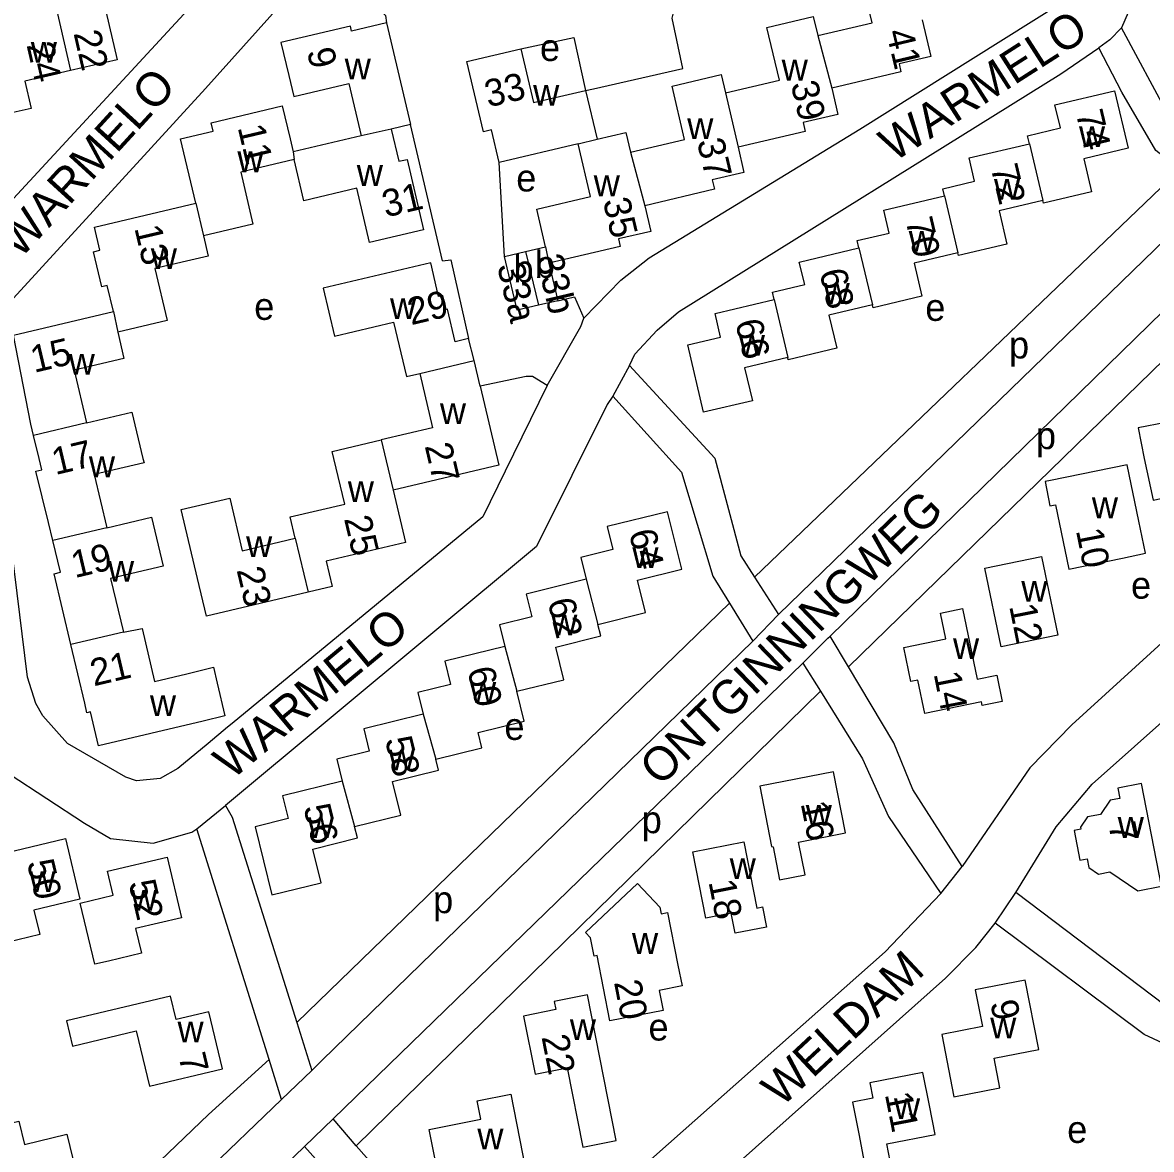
# Model space of a CAD drawing. Extents: x 157646 to 159241, y 379213 to 381217.
# Drawn here: x 158162.1 to 158329.1, y 380397.8 to 380564.5 of the extents above; entities that cross this region are included whole.
import ezdxf

# ---------------------------------------------------------------- set-up
doc = ezdxf.new("R2010")
doc.units = 0
for name, color, linetype in [('BLT_Basislijn', 7, 'Continuous'), ('BLT_Bebouwing', 7, 'Continuous'), ('BLT_Centroide', 7, 'Continuous'), ('BLT_Huisnummer', 7, 'Continuous'), ('BLT_Huisnummer_ tussenligend', 7, 'Continuous'), ('BLT_Onderverdeling_panden', 7, 'Continuous'), ('BLT_Straatnaam', 7, 'Continuous')]:
    doc.layers.add(name, color=color, linetype=linetype)

msp = doc.modelspace()

# ---------------------------------------------------------------- linework, layer by layer
at = {"layer": 'BLT_Basislijn'}
for p, q in [((158233.4, 380529.9), (158232.59, 380543.79)), ((158333.3, 380542.79), (158270.39, 380482.44)), ((158338.15, 380539.27), (158273.9, 380476.9)), ((158281.54, 380473.72), (158341.93, 380532.68)), ((158345.48, 380528.82), (158284.27, 380469.15)), ((158251.9, 380513.75), (158249.43, 380509.21)), ((158270.39, 380482.44), (158273.9, 380476.9)), ((158266.66, 380478.58), (158202.66, 380416.55)), ((158266.66, 380478.58), (158270.13, 380472.97)), ((158273.9, 380476.9), (158270.13, 380472.97)), ((158270.13, 380472.97), (158206.43, 380410.96)), ((158277.5, 380469.74), (158281.24, 380473.43)), ((158281.24, 380473.43), (158281.54, 380473.72)), ((158284.27, 380469.15), (158281.54, 380473.72)), ((158277.5, 380469.74), (158208.05, 380402.3)), ((158277.5, 380469.74), (158280.12, 380465.55)), ((158280.12, 380465.55), (158211.47, 380398.29)), ((158187.89, 380445.21), (158192.12, 380448.67)), ((158198.57, 380411.07), (158187.89, 380445.21)), ((158297.95, 380435.63), (158301.07, 380439.61)), ((158305.95, 380431.25), (158309.01, 380435.78)), ((158202.66, 380416.55), (158204.88, 380409.47)), ((158200.42, 380405.17), (158198.57, 380411.07)), ((158204.88, 380409.47), (158206.43, 380410.96)), ((158200.42, 380405.17), (158204.88, 380409.47)), ((158168.55, 380374.51), (158200.42, 380405.17)), ((158203.81, 380398.22), (158208.05, 380402.3)), ((158211.47, 380398.29), (158208.05, 380402.3)), ((158203.81, 380398.22), (158139.69, 380336.38)), ((158203.81, 380398.22), (158207.13, 380394.51)), ((158211.47, 380398.29), (158231.68, 380375.57))]:
    msp.add_line(p, q, dxfattribs=at)
for points in [[(158175.77, 380635.43), (158161.21, 380631.77), (158156.75, 380630.24), (158148.79, 380625.89), (158142.68, 380620.8), (158139.58, 380617.09), (158122.17, 380593.19), (158088.91, 380548.79), (158087.38, 380546.5), (158085.15, 380541.88), (158083.98, 380537.65), (158083.7, 380528.68), (158092.89, 380456.03), (158094.64, 380453.46), (158097.98, 380452.14), (158149.23, 380463.59), (158151.12, 380464.15), (158152.81, 380465.76), (158153.39, 380468.79), (158147.46, 380517.85), (158147.9, 380522.87), (158148.44, 380524.46), (158150.49, 380527.42), (158204.53, 380585.91)], [(158245.14, 380520.77), (158250.62, 380526.37), (158254.8, 380529.71), (158285.96, 380548.74), (158315.78, 380567.4), (158317.48, 380571.03), (158317.34, 380574.69), (158312.89, 380594.77), (158310.67, 380597.7), (158308.56, 380598.87), (158304.79, 380599.21), (158304.38, 380599.21)], [(158320.81, 380598.41), (158321.35, 380597.47), (158322.52, 380593.15), (158326.84, 380572.7), (158326.63, 380568.3), (158324.66, 380563.71)], [(158245.37, 380554.46), (158246.58, 380554.68), (158259.79, 380557.7), (158258.19, 380565.13), (158258.38, 380565.93), (158277.39, 380570.67), (158277.63, 380570.93), (158277.57, 380571.67), (158274.44, 380584.86)], [(158192.44, 380460.23), (158189.56, 380457.85), (158185.09, 380454.13), (158182.48, 380452.66), (158178.96, 380452.33), (158177.37, 380452.85), (158168.77, 380457.81), (158165.12, 380461.91), (158164.05, 380463.75), (158162.83, 380467.65), (158157.4, 380511.32), (158157.32, 380517.6), (158158.75, 380521.1), (158160.25, 380523.11), (158189.19, 380554.74), (158206.48, 380574.08)], [(158206.48, 380574.08), (158215.77, 380565.54), (158215.93, 380564.47)], [(158324.66, 380563.71), (158322.93, 380561.92), (158321.31, 380560.74)], [(158337.01, 380546.43), (158331.69, 380550.62), (158324.66, 380563.71)], [(158235.82, 380560.61), (158243.66, 380562.28), (158245.37, 380554.46)], [(158251.9, 380513.75), (158252.68, 380515.43), (158255.97, 380519), (158259.14, 380521.72), (158315.7, 380556.9), (158321.31, 380560.74)], [(158333.3, 380542.79), (158329.75, 380545.57), (158324.69, 380554.22), (158321.31, 380560.74)], [(158223.04, 380534.29), (158219.48, 380549.41)], [(158224.23, 380529.23), (158223.04, 380534.29)], [(158224.23, 380529.23), (158225.44, 380529.38), (158228.06, 380517.74)], [(158241.26, 380523.34), (158243.77, 380523.9), (158245.14, 380520.77)], [(158239.71, 380510.81), (158244.69, 380519.51), (158245.14, 380520.77)], [(158251.9, 380513.75), (158264.49, 380500.04), (158268.37, 380485.62), (158270.39, 380482.44)], [(158239.71, 380510.81), (158237.54, 380512.11), (158236.62, 380512.12), (158229.79, 380510.68)], [(158239.71, 380510.81), (158233.48, 380498.11), (158230.19, 380491.38), (158193.09, 380460.77), (158192.44, 380460.23)], [(158249.43, 380509.21), (158248.57, 380508), (158238.14, 380486.99), (158192.12, 380448.67)], [(158249.43, 380509.21), (158259.56, 380497.97), (158264.2, 380482.57), (158266.66, 380478.58)], [(158356.9, 380495.51), (158352.76, 380492.88), (158317.31, 380460.61), (158311.07, 380454.22), (158301.07, 380439.61)], [(158309.01, 380435.78), (158314.99, 380445.5), (158320.3, 380451.83), (158358.31, 380485.67), (158360.33, 380487), (158361.92, 380487.62), (158364.63, 380487.17), (158366, 380486.42), (158393.52, 380468.6), (158394.86, 380467.01), (158394.65, 380464.96), (158391.74, 380460.19), (158356.18, 380404.83)], [(158301.07, 380439.61), (158293.78, 380451.01), (158290.96, 380457.94), (158284.27, 380469.15)], [(158280.12, 380465.55), (158286.35, 380455.55), (158290.21, 380447.05), (158297.95, 380435.63)], [(158120.42, 380373.18), (158106.09, 380387.68), (158103.09, 380391.83), (158100.74, 380396.83), (158099.57, 380401.3), (158094.64, 380437.58), (158094.86, 380440.54), (158096.96, 380442.3), (158149.84, 380454.92), (158155.25, 380454.84), (158160.12, 380453.33), (158171.27, 380446.02), (158175.14, 380443.78), (158181.44, 380443.07), (158187.17, 380444.7), (158187.89, 380445.21)], [(158192.12, 380448.67), (158193.12, 380446.92), (158202.66, 380416.55)], [(158231.68, 380375.57), (158289.69, 380427.01), (158297.95, 380435.63)], [(158356.18, 380404.83), (158341.81, 380414.09), (158331.1, 380419.09), (158309.01, 380435.78)], [(158245.11, 380375.43), (158298.61, 380423.12), (158303.1, 380427.63), (158305.95, 380431.25)], [(158353.1, 380400.13), (158337.01, 380410.59), (158328.02, 380414.79), (158305.95, 380431.25)], [(158164.52, 380378.86), (158189.62, 380402.94), (158198.57, 380411.07)]]:
    msp.add_lwpolyline(points, dxfattribs=at)
at = {"layer": 'BLT_Bebouwing'}
for p, q in [((158215.93, 380564.47), (158219.48, 380549.41)), ((158245.37, 380554.46), (158247.08, 380547.23)), ((158219.48, 380549.41), (158216.65, 380548.75)), ((158212.2, 380547.73), (158202.13, 380545.36)), ((158244.27, 380546.55), (158232.59, 380543.79)), ((158221.43, 380533.84), (158213.42, 380531.95)), ((158236.52, 380530.63), (158239.47, 380531.33)), ((158233.4, 380529.9), (158236.52, 380530.63)), ((158222.48, 380528.93), (158206.56, 380525.18)), ((158241.26, 380523.34), (158238.4, 380522.67)), ((158176.2, 380518.68), (158177.11, 380514.81)), ((158228.89, 380514.48), (158228.06, 380517.74)), ((158229.79, 380510.68), (158228.89, 380514.48)), ((158171.59, 380505.27), (158178.29, 380506.85)), ((158174.57, 380489.75), (158181.19, 380491.31)), ((158181.19, 380491.31), (158182.9, 380484.08)), ((158204.34, 380480.23), (158189.31, 380476.68)), ((158186.39, 380468.16), (158190.34, 380469.11)), ((158192.04, 380461.9), (158188.83, 380461.14))]:
    msp.add_line(p, q, dxfattribs=at)
for points in [[(158279.73, 380562.58), (158287.75, 380564.47), (158285.91, 380572.27), (158293.05, 380573.96)], [(158173.74, 380569.18), (158176.09, 380558.98), (158169.19, 380557.39)], [(158266.08, 380554.12), (158274.05, 380556), (158272.21, 380563.77), (158279.07, 380565.39), (158279.73, 380562.58)], [(158295.19, 380564.9), (158296.47, 380559.49), (158291.75, 380558.38), (158292.03, 380557.2), (158281.8, 380554.78)], [(158215.93, 380564.47), (158210.78, 380563.25), (158210.61, 380563.98), (158200.33, 380561.55), (158201.48, 380556.69), (158202.21, 380553.55), (158210.38, 380555.48), (158212.2, 380547.73)], [(158232.59, 380543.79), (158231.46, 380548.61), (158230.27, 380548.33), (158227.81, 380558.72), (158235.82, 380560.61)], [(158235.82, 380560.61), (158237.69, 380552.65), (158245.37, 380554.46)], [(158169.19, 380557.39), (158162.46, 380555.85), (158163.39, 380551.8), (158159.38, 380550.88)], [(158252.05, 380545.33), (158260.03, 380547.22), (158258.17, 380555.08), (158265.45, 380556.8), (158266.08, 380554.12)], [(158281.8, 380554.78), (158282.71, 380550.91), (158277.55, 380549.69), (158277.86, 380548.38), (158267.94, 380546.04)], [(158311.02, 380546.58), (158310.75, 380547.76), (158315.61, 380548.9), (158314.81, 380552.31), (158323.62, 380554.39), (158325.62, 380545.91), (158319.07, 380544.36), (158320.23, 380539.47), (158313.1, 380537.79), (158313.01, 380538.15)], [(158187.74, 380537.78), (158185.49, 380547.31), (158190.29, 380548.44), (158189.99, 380549.68), (158200.52, 380552.17), (158201.67, 380547.3), (158202.13, 380545.36)], [(158216.65, 380548.75), (158217.77, 380543.98), (158218.98, 380544.26), (158221.43, 380533.84)], [(158247.08, 380547.23), (158251.36, 380548.24), (158252.05, 380545.33)], [(158239.47, 380531.33), (158238.16, 380536.89), (158246.11, 380538.76), (158244.27, 380546.55)], [(158298.46, 380538.86), (158298.21, 380539.91), (158302.92, 380541.02), (158302.1, 380544.47), (158311.02, 380546.58)], [(158267.94, 380546.04), (158268.81, 380542.33), (158264.11, 380541.22), (158264.44, 380539.83), (158254.13, 380537.4)], [(158202.28, 380544.24), (158194.37, 380542.37), (158196.19, 380534.67), (158188.86, 380532.94)], [(158213.42, 380531.95), (158211.53, 380539.98), (158203.72, 380538.14), (158202.28, 380544.24)], [(158175.55, 380521.76), (158174.64, 380525.59), (158173.81, 380525.4), (158172.59, 380530.59), (158173.55, 380530.82), (158172.74, 380534.24), (158187.74, 380537.78)], [(158285.82, 380531.15), (158285.56, 380532.25), (158290.28, 380533.36), (158289.48, 380536.74), (158298.46, 380538.86)], [(158313.01, 380538.15), (158306.54, 380536.62), (158307.7, 380531.7), (158300.55, 380530.01), (158300.45, 380530.43)], [(158254.13, 380537.4), (158255.03, 380533.61), (158250.26, 380532.48), (158250.51, 380531.39), (158239.95, 380528.89)], [(158188.86, 380532.94), (158189.56, 380529.96), (158181.66, 380528.1), (158183.48, 380520.4), (158176.2, 380518.68)], [(158273.26, 380523.53), (158273.01, 380524.6), (158277.79, 380525.73), (158277, 380529.06), (158285.82, 380531.15)], [(158238.4, 380522.67), (158235.27, 380521.93), (158233.4, 380529.9)], [(158300.45, 380530.43), (158293.97, 380528.9), (158295.12, 380524.01), (158287.9, 380522.31), (158287.8, 380522.75)], [(158228.06, 380517.74), (158226.1, 380517.28), (158224.96, 380522.08), (158224.75, 380522.03), (158224.25, 380524.13), (158223.65, 380523.98), (158222.48, 380528.93)], [(158239.95, 380528.89), (158241.26, 380523.34)], [(158206.56, 380525.18), (158208.23, 380518.09), (158216.99, 380520.15), (158218.89, 380512.12), (158220.85, 380512.59)], [(158275.29, 380514.94), (158268.9, 380513.43), (158270.06, 380508.53), (158262.85, 380506.83), (158260.49, 380516.83), (158265.36, 380517.97), (158264.53, 380521.47), (158273.26, 380523.53)], [(158287.8, 380522.75), (158281.37, 380521.23), (158282.53, 380516.31), (158275.37, 380514.62), (158275.29, 380514.94)], [(158163.74, 380503.42), (158163.35, 380505.08), (158160.75, 380518.27), (158175.55, 380521.76)], [(158177.11, 380514.81), (158169.75, 380513.08), (158171.59, 380505.27)], [(158220.85, 380512.59), (158222.75, 380504.53), (158215.15, 380502.74)], [(158229.79, 380510.68), (158232.54, 380499), (158216.91, 380495.3)], [(158336.22, 380500), (158335.8, 380502.15), (158339.09, 380502.79), (158337.64, 380510.32), (158330.53, 380508.95), (158331.22, 380505.35), (158327.13, 380504.56), (158328.01, 380499.99), (158329.31, 380493.82), (158337.18, 380495.44), (158336.22, 380500)], [(158178.29, 380506.85), (158179.91, 380499.99), (158180.1, 380499.38)], [(158166.6, 380487.87), (158165.96, 380490.54), (158164.07, 380498.13), (158164.94, 380498.34), (158164.55, 380500), (158163.74, 380503.42)], [(158202.45, 380488.21), (158201.71, 380491.35), (158209.76, 380493.25), (158208.15, 380500), (158207.91, 380501.03), (158215.15, 380502.74)], [(158180.1, 380499.38), (158172.7, 380497.63), (158174.57, 380489.75)], [(158324.81, 380485.27), (158328.18, 380485.97), (158327.2, 380490.75), (158325.49, 380499.08), (158314.17, 380496.76)], [(158314.17, 380496.76), (158313.34, 380496.58), (158314.07, 380493.02), (158314.91, 380493.16), (158316.87, 380483.64), (158324.81, 380485.27)], [(158216.91, 380495.3), (158218.74, 380487.57), (158207.02, 380484.8), (158207.9, 380481.08), (158204.34, 380480.23)], [(158185.58, 380492.44), (158192.75, 380494.14), (158194.59, 380486.36), (158202.45, 380488.21)], [(158189.31, 380476.68), (158187.99, 380482.24), (158185.58, 380492.44)], [(158247.21, 380475.46), (158254.26, 380477.19), (158253.07, 380482.01), (158259.61, 380483.61), (158257.52, 380492.13), (158248.6, 380489.94), (158249.43, 380486.55), (158244.66, 380485.37), (158245.46, 380482.13)], [(158169.25, 380472.46), (158166.77, 380482.94), (158167.71, 380483.16), (158166.6, 380487.87)], [(158304.44, 380483.76), (158312.81, 380485.48), (158315.21, 380473.84), (158306.84, 380472.12), (158304.44, 380483.76)], [(158182.9, 380484.08), (158175.14, 380482.24), (158177.02, 380474.3)], [(158245.46, 380482.13), (158236.59, 380479.95), (158237.42, 380476.58), (158232.64, 380475.4), (158233.43, 380472.19)], [(158304.04, 380463.43), (158303.92, 380464.01), (158295.55, 380462.29), (158294.54, 380467.19), (158293.49, 380466.98), (158292.45, 380472.04), (158298.68, 380473.32), (158297.89, 380477.13), (158301.14, 380477.8), (158303.29, 380467.34), (158306.21, 380467.93), (158307.01, 380464.04), (158304.04, 380463.43)], [(158177.02, 380474.3), (158179.78, 380474.86), (158181.63, 380467.01), (158186.39, 380468.16)], [(158235.2, 380465.56), (158242.15, 380467.27), (158240.97, 380472.1), (158247.63, 380473.74), (158247.21, 380475.46)], [(158188.83, 380461.14), (158173.36, 380457.48), (158172.17, 380462.51), (158171.63, 380462.38), (158171.3, 380463.8), (158169.25, 380472.46)], [(158233.43, 380472.19), (158224.55, 380470.01), (158225.39, 380466.58), (158220.57, 380465.4), (158221.37, 380462.15)], [(158190.34, 380469.11), (158190.89, 380466.76), (158192.04, 380461.9)], [(158223.22, 380455.5), (158230.05, 380457.17), (158229.49, 380459.45), (158236.29, 380461.12), (158235.2, 380465.56)], [(158221.37, 380462.15), (158212.57, 380459.99), (158213.38, 380456.7), (158208.59, 380455.52), (158209.38, 380452.28)], [(158211.23, 380445.55), (158218.07, 380447.23), (158216.85, 380452.21), (158223.62, 380453.88), (158223.22, 380455.5)], [(158271.14, 380451.51), (158272.89, 380442.61), (158273.13, 380442.53), (158274.08, 380437.67), (158277.85, 380438.42), (158276.9, 380443.22), (158283.83, 380444.59), (158282.04, 380453.66), (158271.14, 380451.51)], [(158209.38, 380452.28), (158200.54, 380450.11), (158201.38, 380446.71), (158196.52, 380445.52), (158199, 380435.43), (158206.26, 380437.21), (158205.03, 380442.22), (158211.65, 380443.85), (158211.23, 380445.55)], [(158318.49, 380440.58), (158319.58, 380440.79), (158319.84, 380439.46), (158321.24, 380438.51), (158322.94, 380438.84), (158327.08, 380436.05), (158330.55, 380436.72), (158327.61, 380451.91), (158324.09, 380451.23), (158324.39, 380449.71), (158322.95, 380449.43), (158321.54, 380447.34), (158319.6, 380446.96), (158318.58, 380445.45), (158318.64, 380445.15), (158317.64, 380444.96), (158318.49, 380440.58)], [(158155.61, 380436.97), (158160.47, 380438.13), (158159.63, 380441.66), (158168.46, 380443.76), (158170.59, 380434.8), (158163.79, 380433.19), (158164.66, 380429.55), (158159.79, 380428.39), (158157.76, 380427.91), (158155.61, 380436.97)], [(158261.24, 380441.78), (158268.78, 380443.27), (158270.71, 380433.49), (158271.56, 380433.66), (158272.15, 380430.67), (158267.5, 380429.75), (158266.91, 380432.74), (158263.17, 380432), (158261.24, 380441.78)], [(158174.83, 380425.65), (158172.8, 380425.16), (158170.65, 380434.23), (158175.51, 380435.39), (158174.67, 380438.92), (158183.51, 380441.01), (158185.63, 380432.06), (158178.83, 380430.44), (158179.7, 380426.8), (158174.83, 380425.65)], [(158246.66, 380426.36), (158246.12, 380429.06), (158245.35, 380429.88), (158253.07, 380437.14), (158256.37, 380433.62), (158256.56, 380432.63), (158257.52, 380432.82), (158259.05, 380425.05), (158259.66, 380421.96), (158256.27, 380421.29), (158256.85, 380418.35), (158248.99, 380416.8), (158247.09, 380426.45)], [(158247.09, 380426.45), (158246.66, 380426.36)], [(158310.39, 380422.83), (158303.02, 380421.39), (158304.08, 380415.97), (158298.06, 380414.79), (158299.87, 380405.55), (158306.67, 380406.88), (158305.81, 380411.26), (158312.4, 380412.55), (158310.39, 380422.83)], [(158191.66, 380409.69), (158189.66, 380418.12), (158184.82, 380416.97), (158184, 380420.45), (158168.59, 380416.79), (158169.48, 380413.05), (158178.93, 380415.3), (158180.87, 380407.13), (158191.66, 380409.69)], [(158237.91, 380408.92), (158242.65, 380409.85), (158244.97, 380398.11), (158249.93, 380399.09), (158245.68, 380420.62), (158240.72, 380419.65), (158240.96, 380418.45), (158236.21, 380417.51), (158237.91, 380408.92)], [(158296.25, 380404.26), (158295.29, 380409.16), (158287.43, 380407.62), (158287.87, 380405.34), (158284.87, 380404.75), (158285.83, 380399.85), (158286.71, 380395.33), (158290.42, 380396.05), (158289.93, 380398.6), (158297.08, 380400), (158296.25, 380404.26)], [(158234.08, 380389.63), (158233.47, 380392.69), (158224.2, 380390.86), (158222.25, 380400.74), (158229.87, 380402.24), (158229.33, 380404.97), (158234.32, 380405.95), (158237.41, 380390.29), (158234.08, 380389.63)], [(158169.98, 380394.55), (158171.21, 380389.38), (158162.74, 380387.37), (158161.56, 380392.38), (158156.84, 380391.26), (158155.93, 380395.08), (158154.68, 380400.34), (158161.56, 380401.97), (158162.38, 380398.51), (158168.68, 380400.01), (158169.98, 380394.55)]]:
    msp.add_lwpolyline(points, dxfattribs=at)
at = {"layer": 'BLT_Onderverdeling_panden'}
for p, q in [((158167.16, 380566.23), (158169.19, 380557.39)), ((158279.73, 380562.58), (158281.8, 380554.78)), ((158266.08, 380554.12), (158267.94, 380546.04)), ((158216.65, 380548.75), (158212.2, 380547.73)), ((158244.27, 380546.55), (158247.08, 380547.23)), ((158311.02, 380546.58), (158313.01, 380538.15)), ((158202.13, 380545.36), (158202.28, 380544.24)), ((158252.05, 380545.33), (158254.13, 380537.4)), ((158187.74, 380537.78), (158188.86, 380532.94)), ((158298.46, 380538.86), (158300.45, 380530.43)), ((158239.47, 380531.33), (158239.95, 380528.89)), ((158285.82, 380531.15), (158287.8, 380522.75)), ((158236.52, 380530.63), (158238.4, 380522.67)), ((158273.26, 380523.53), (158275.29, 380514.94)), ((158175.55, 380521.76), (158176.2, 380518.68)), ((158220.85, 380512.59), (158228.89, 380514.48)), ((158171.59, 380505.27), (158163.74, 380503.42)), ((158215.15, 380502.74), (158216.91, 380495.3)), ((158174.57, 380489.75), (158166.6, 380487.87)), ((158202.45, 380488.21), (158204.34, 380480.23)), ((158245.46, 380482.13), (158247.21, 380475.46)), ((158177.02, 380474.3), (158169.25, 380472.46)), ((158233.43, 380472.19), (158235.2, 380465.56)), ((158221.37, 380462.15), (158223.22, 380455.5)), ((158209.38, 380452.28), (158211.23, 380445.55))]:
    msp.add_line(p, q, dxfattribs=at)

# ---------------------------------------------------------------- texts
at = {"layer": 'BLT_Centroide'}
for s, p in [('w', (158163.33, 380558.56)), ('e', (158238.64, 380558.81)), ('w', (158209.76, 380556.09)), ('w', (158274.39, 380555.92)), ('w', (158237.63, 380552.19)), ('w', (158260.42, 380547.25)), ('w', (158318.36, 380546.09)), ('w', (158193.89, 380542.36)), ('w', (158211.55, 380540.34)), ('e', (158235.13, 380539.51)), ('w', (158246.59, 380538.8)), ('w', (158305.79, 380538.28)), ('w', (158293.18, 380530.59)), ('w', (158181.08, 380528.03)), ('b', (158234.72, 380526.07)), ('b', (158237.87, 380526.73)), ('w', (158280.59, 380522.88)), ('e', (158196.37, 380520.51)), ('w', (158216.46, 380520.62)), ('e', (158295.63, 380520.36)), ('w', (158268.05, 380515.19)), ('p', (158308.01, 380514.8)), ('w', (158168.94, 380512.41)), ('w', (158223.84, 380505.11)), ('p', (158311.99, 380501.39)), ('w', (158171.92, 380497.23)), ('w', (158210.22, 380493.56)), ('w', (158320.27, 380491.17)), ('w', (158195.17, 380485.41)), ('w', (158252.3, 380483.78)), ('w', (158174.75, 380481.77)), ('w', (158309.83, 380478.8)), ('e', (158326.06, 380479.26)), ('w', (158240.31, 380473.84)), ('w', (158299.73, 380470.33)), ('w', (158228.29, 380463.84)), ('w', (158180.95, 380461.89)), ('e', (158233.38, 380458.36)), ('w', (158216.26, 380453.84)), ('p', (158253.68, 380444.56)), ('w', (158277.95, 380445.66)), ('w', (158204.29, 380443.84)), ('w', (158324.09, 380443.86)), ('w', (158266.7, 380437.77)), ('w', (158163.11, 380435.84)), ('w', (158178.16, 380433.09)), ('p', (158222.83, 380432.73)), ('w', (158252.25, 380426.7)), ('w', (158185.03, 380413.62)), ('w', (158243.06, 380413.94)), ('e', (158254.69, 380413.88)), ('w', (158305.23, 380414.2)), ('w', (158291, 380402.25)), ('w', (158229.38, 380397.78)), ('e', (158316.62, 380398.73))]:
    msp.add_text(s, height=4, dxfattribs=at).set_placement(p)
at = {"layer": 'BLT_Huisnummer'}
for s, rotation, p in [('22', 282.9451, (158169.63, 380562.93)), ('41', 283.2852, (158289.82, 380563.11)), ('24', 282.9451, (158162.68, 380561.2)), ('9', 283.2639, (158204.14, 380560.31)), ('33', 13.2856, (158230.98, 380551.93)), ('39', 283.2792, (158275.71, 380555.42)), ('74', 283.2824, (158317.87, 380551.13)), ('11', 283.2639, (158193.91, 380549)), ('37', 283.2884, (158261.83, 380546.93)), ('31', 13.2716, (158215.82, 380535.65)), ('35', 283.2791, (158247.92, 380538.13)), ('70', 283.2824, (158292.68, 380535.23)), ('13', 283.2639, (158178.63, 380534.11)), ('33b', 283.2791, (158238.04, 380529.75)), ('33a', 283.2791, (158232.28, 380528.52)), ('29', 13.2704, (158219.58, 380519.71)), ('66', 283.2824, (158267.49, 380520.18)), ('15', 13.2722, (158163.82, 380512.66)), ('27', 283.2676, (158221.57, 380501.87)), ('25', 283.305, (158209.64, 380491.1)), ('64', 283.8113, (158251.76, 380489.07)), ('10', 281.2362, (158317.9, 380489.35)), ('23', 283.3186, (158193.75, 380483.52)), ('12', 281.2362, (158308.03, 380478.17)), ('21', 13.2722, (158172.64, 380466.28)), ('60', 283.8113, (158227.86, 380468.72)), ('14', 281.2362, (158296.86, 380468.15)), ('56', 283.8022, (158203.62, 380448.4)), ('16', 281.1638, (158277.19, 380448.97)), ('7', 280.9548, (158322.7, 380445.85)), ('50', 283.367, (158162.73, 380440.23)), ('52', 283.367, (158177.77, 380437.21)), ('18', 281.1638, (158263.55, 380437.37)), ('20', 281.1638, (158249.57, 380422.51)), ('9', 281.0892, (158305.23, 380419.52)), ('22', 281.1638, (158238.85, 380414.42)), ('7', 283.3606, (158185.14, 380411.59)), ('11', 281.0892, (158289.64, 380405.93))]:
    msp.add_text(s, height=4, rotation=rotation, dxfattribs=at).set_placement(p)
at = {"layer": 'BLT_Huisnummer_ tussenligend'}
for s, rotation, p in [('72', 283.2824, (158305.28, 380543.09)), ('68', 283.2824, (158279.94, 380527.63)), ('17', 13.2722, (158166.96, 380497.54)), ('19', 13.2722, (158169.83, 380482.29)), ('62', 283.8113, (158239.74, 380478.88)), ('58', 283.8113, (158215.69, 380458.4))]:
    msp.add_text(s, height=4, rotation=rotation, dxfattribs=at).set_placement(p)
at = {"layer": 'BLT_Straatnaam'}
for s, rotation, p in [('WARMELO', 32.6243, (158290.96, 380543.78)), ('WARMELO', 47.5541, (158161.75, 380529.4)), ('ONTGINNINGWEG', 44.0133, (158256.4, 380451.34)), ('WARMELO', 39.7834, (158193.06, 380452.35)), ('WELDAM', 43.0134, (158274.35, 380403.9))]:
    msp.add_text(s, height=5, rotation=rotation, dxfattribs=at).set_placement(p)

doc.saveas('drawing.dxf')
